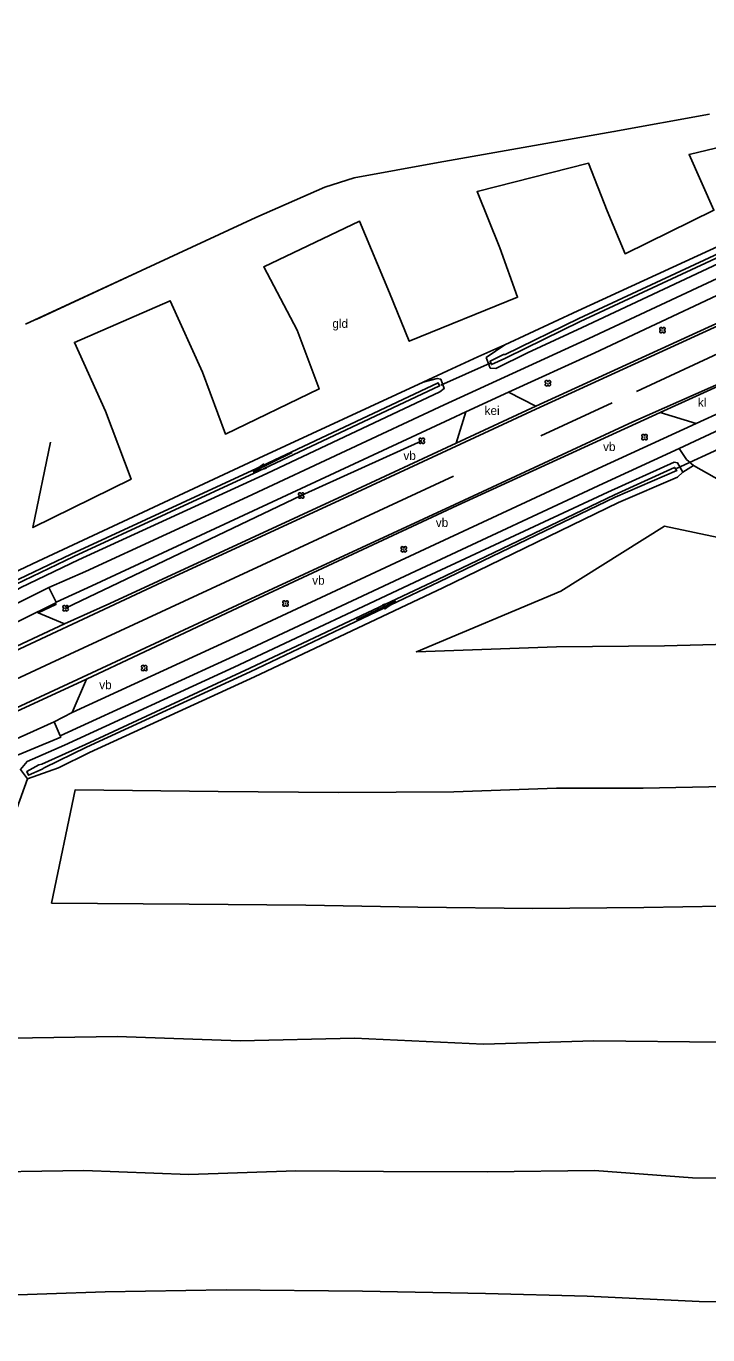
# Model space of a CAD drawing. Extents: x 154825 to 158680, y 370717 to 378075.
# Drawn here: x 157644.3 to 157722.1, y 372726.8 to 372876 of the extents above; entities that cross this region are included whole.
import ezdxf

# ---------------------------------------------------------------- set-up
doc = ezdxf.new("R2010")
doc.units = 0
for name, color, linetype in [('boom', 7, 'Continuous'), ('breuklijn', 7, 'Continuous'), ('cultuurscheiding', 7, 'Continuous'), ('deelstreep(3-9)', 7, 'Continuous'), ('duiker lijn', 7, 'Continuous'), ('grasland_productiegrasl(vs)', 7, 'Continuous'), ('hoogteverschillijn', 7, 'Continuous'), ('insteek sloot', 7, 'Continuous'), ('kantstreep', 7, 'Continuous'), ('keiverharding(vs)', 7, 'Continuous'), ('klinkerverharding(vs)', 7, 'Continuous'), ('maaiveldlijn algemeen - gesloten verharding', 7, 'Continuous'), ('maaiveldlijn algemeen - open verharding', 7, 'Continuous'), ('maaiveldlijn algemeen - tegelverharding', 7, 'Continuous'), ('raster - hek', 7, 'Continuous'), ('raster_hekw+inst', 7, 'Continuous'), ('Sloot bodem', 7, 'Continuous'), ('stroomrichting  watergangen', 7, 'Continuous'), ('verkeersb_z kabel', 7, 'Continuous'), ('vlak_akkerland', 7, 'Continuous'), ('vlak_Grasland', 7, 'Continuous'), ('vlak_Grazige_vegetatie', 7, 'Continuous')]:
    doc.layers.add(name, color=color, linetype=linetype)

msp = doc.modelspace()

# ---------------------------------------------------------------- linework, layer by layer
at = {"layer": 'boom'}
msp.add_lwpolyline([(157689.42, 372828.76), (157675.68, 372822.52), (157648.8, 372809.66)], dxfattribs=at)
for centre in [(157716.88, 372841.38), (157703.82, 372835.32), (157689.42, 372828.76), (157714.85, 372829.18), (157675.68, 372822.52), (157687.38, 372816.39), (157673.89, 372810.2), (157648.8, 372809.66), (157657.78, 372802.84)]:
    msp.add_circle(centre, 0.006, dxfattribs=at)
for centre, start, end in [((157716.72, 372841.54), 357.075, 272.925), ((157717.04, 372841.54), 267.075, 182.925), ((157716.72, 372841.22), 87.075, 2.925), ((157717.04, 372841.22), 177.075, 92.925), ((157703.66, 372835.48), 357.075, 272.925), ((157703.98, 372835.48), 267.075, 182.925), ((157703.66, 372835.16), 87.075, 2.925), ((157703.98, 372835.16), 177.075, 92.925), ((157689.27, 372828.92), 357.075, 272.925), ((157689.27, 372828.6), 87.075, 2.925), ((157689.58, 372828.92), 267.075, 182.925), ((157689.58, 372828.6), 177.075, 92.925), ((157714.69, 372829.34), 357.075, 272.925), ((157714.69, 372829.02), 87.075, 2.925), ((157715, 372829.34), 267.075, 182.925), ((157715, 372829.02), 177.075, 92.925), ((157675.52, 372822.68), 357.075, 272.925), ((157675.52, 372822.36), 87.075, 2.925), ((157675.83, 372822.68), 267.075, 182.925), ((157675.83, 372822.36), 177.075, 92.925), ((157687.22, 372816.54), 357.075, 272.925), ((157687.22, 372816.23), 87.075, 2.925), ((157687.54, 372816.54), 267.075, 182.925), ((157687.54, 372816.23), 177.075, 92.925), ((157673.73, 372810.36), 357.075, 272.925), ((157673.73, 372810.05), 87.075, 2.925), ((157674.05, 372810.36), 267.075, 182.925), ((157674.05, 372810.05), 177.075, 92.925), ((157648.65, 372809.82), 357.075, 272.925), ((157648.65, 372809.5), 87.075, 2.925), ((157648.96, 372809.82), 267.075, 182.925), ((157648.96, 372809.5), 177.075, 92.925), ((157657.62, 372803), 357.075, 272.925), ((157657.62, 372802.69), 87.075, 2.925), ((157657.93, 372803), 267.075, 182.925), ((157657.93, 372802.69), 177.075, 92.925)]:
    msp.add_arc(centre, 0.158, start, end, dxfattribs=at)
at = {"layer": 'breuklijn'}
msp.add_lwpolyline([(157587.11, 372729.57), (157594.94, 372731.25), (157612.07, 372732.63), (157623.63, 372737.63), (157631.2, 372747.28), (157634.47, 372759.97), (157641.12, 372779.89), (157643.22, 372786.82), (157644.44, 372790.21)], dxfattribs=at)
at = {"layer": 'cultuurscheiding'}
msp.add_lwpolyline([(157719.21, 372825.17), (157720.42, 372825.93)], dxfattribs=at)
at = {"layer": 'deelstreep(3-9)'}
msp.add_lwpolyline([(157693.04, 372824.71), (157671.19, 372814.57), (157649.3, 372804.41), (157627.44, 372794.27), (157604.56, 372783.62), (157594.54, 372778.92), (157572.69, 372768.8), (157551.11, 372758.81), (157529.26, 372748.71), (157507.38, 372738.56), (157474.53, 372723.31), (157452.88, 372713.29), (157431.04, 372703.17), (157418.74, 372697.46), (157398.09, 372687.91), (157373.81, 372676.65), (157351.94, 372666.54), (157329.99, 372656.33)], dxfattribs=at)
at = {"layer": 'duiker lijn'}
for points in [[(157691.59, 372835.12), (157697.22, 372837.6)], [(157718.5, 372825.61), (157729.04, 372830.46)]]:
    msp.add_lwpolyline(points, dxfattribs=at)
at = {"layer": 'hoogteverschillijn'}
for points in [[(157645.43, 372842.58), (157657.45, 372848.19), (157670.51, 372854.24), (157678.38, 372857.67), (157681.73, 372858.74), (157691.3, 372860.49), (157711.35, 372864.02), (157722.23, 372866.02)], [(157729.57, 372863.72), (157719.92, 372861.42), (157722.75, 372855.05), (157712.62, 372850.1), (157710.59, 372854.99), (157708.45, 372860.41), (157695.74, 372857.19), (157698.33, 372850.77), (157700.36, 372845.14), (157688, 372840.12), (157685.75, 372845.64), (157682.33, 372853.8), (157671.41, 372848.6), (157675.23, 372841.37), (157677.73, 372834.67), (157667.03, 372829.53), (157664.4, 372836.59), (157660.74, 372844.74), (157649.8, 372839.98), (157653.36, 372832.14), (157656.26, 372824.37), (157645.08, 372818.87), (157647.07, 372828.61)], [(157734.61, 372805.82), (157717.11, 372805.36), (157704.8, 372805.27), (157688.82, 372804.71), (157705.28, 372811.63), (157717.1, 372819.03), (157732.77, 372815.73)], [(157728.1, 372775.77), (157714.76, 372775.52), (157702.1, 372775.42), (157688.99, 372775.56), (157676.22, 372775.79), (157662.89, 372775.92), (157647.21, 372776.04), (157649.89, 372788.94), (157666.22, 372788.75), (157679.92, 372788.64), (157693.08, 372788.73), (157704.81, 372789.14), (157714.7, 372789.16), (157724.02, 372789.35)], [(157642.64, 372760.62), (157654.69, 372760.81), (157668.71, 372760.32), (157681.74, 372760.64), (157696.46, 372759.93), (157709.07, 372760.34), (157723.63, 372760.19)], [(157639.97, 372731.24), (157653.31, 372731.72), (157667.11, 372731.93), (157682.68, 372731.78), (157696.7, 372731.51), (157708.31, 372731.21), (157721.08, 372730.61), (157731.24, 372730.43), (157736.41, 372730.09), (157741.03, 372744.34), (157731.27, 372744.59), (157720.31, 372744.69), (157709.14, 372745.53), (157696.93, 372745.39), (157685.05, 372745.44), (157675.08, 372745.51), (157662.84, 372745.08), (157650.89, 372745.54), (157636.49, 372745.31)]]:
    msp.add_lwpolyline(points, dxfattribs=at)
at = {"layer": 'insteek sloot'}
for points in [[(157751.9, 372864.24), (157752.78, 372863.92), (157752.1, 372862.41), (157743.23, 372858.24), (157732.59, 372853.35), (157707.71, 372841.7), (157701.49, 372838.79), (157697.86, 372837.02), (157697.23, 372837.05), (157696.78, 372838.25), (157698.92, 372839.7)], [(157689.59, 372835.43), (157691.19, 372835.87), (157691.59, 372835.78), (157692, 372834.72), (157691.48, 372834.35), (157671.74, 372825.02), (157650.28, 372815.17), (157643.7, 372812.04), (157640.77, 372810.28), (157639.96, 372810.48), (157639.54, 372811.41), (157639.75, 372811.99), (157641.4, 372813.01)], [(157644.44, 372790.21), (157643.64, 372791.27), (157644.41, 372792.19), (157648.67, 372794.06), (157668.04, 372802.96), (157690.49, 372813.51), (157710.64, 372822.89), (157718.2, 372826.32), (157718.6, 372826.23), (157719.21, 372825.17)], [(157719.21, 372825.17), (157718.61, 372824.62), (157711.88, 372821.74), (157691.83, 372811.98), (157670.33, 372801.83), (157651.54, 372793.2), (157647.98, 372791.46), (157644.44, 372790.21)]]:
    msp.add_lwpolyline(points, dxfattribs=at)
at = {"layer": 'kantstreep'}
for points in [[(157810.64, 372876.05), (157801.79, 372871.94), (157775.86, 372859.77), (157754.32, 372849.16), (157753.47, 372848.81), (157743.28, 372844.03), (157725.96, 372836.42), (157713.52, 372830.91), (157693.18, 372821.51), (157668.95, 372810.3), (157650.14, 372801.55), (157633.01, 372793.59), (157612.56, 372784.08), (157591.65, 372774.31), (157568.57, 372763.65), (157543.05, 372751.84), (157518.22, 372740.35), (157495.3, 372729.73), (157482.15, 372723.63), (157473.39, 372719.56)], [(157758.12, 372858.41), (157746.58, 372853.32), (157739.86, 372850.21), (157734.79, 372847.6), (157723.69, 372842.09), (157702.45, 372832.35), (157680.99, 372822.41), (157659.83, 372812.62), (157637.52, 372802.23), (157632.78, 372800), (157617.21, 372792.78), (157595.92, 372782.87), (157569.75, 372770.75), (157543.55, 372758.61), (157517.06, 372746.36), (157486.41, 372732.15), (157469.86, 372724.47), (157454.4, 372717.29), (157430.13, 372706.05), (157404.83, 372694.32), (157376.21, 372681.02), (157354.77, 372671.07), (157328.63, 372658.97)], [(157729.2, 372841.48), (157735.46, 372844.21), (157736.24, 372844.56), (157738.92, 372845.67), (157741.38, 372846.55), (157741.3, 372847.47), (157738.07, 372845.78), (157733.78, 372843.67), (157729.2, 372841.48), (157713.91, 372834.37)], [(157711.16, 372833.08), (157703, 372829.32)]]:
    msp.add_lwpolyline(points, dxfattribs=at)
at = {"layer": 'maaiveldlijn algemeen - gesloten verharding'}
for points in [[(157759.78, 372864.31), (157751.08, 372860.26), (157729.63, 372850.3), (157708.49, 372840.44), (157691.99, 372832.86), (157669.54, 372822.37), (157651.06, 372813.84), (157646.9, 372812.04)], [(157749.86, 372857.68), (157730.06, 372848.6), (157709.18, 372838.81), (157699.32, 372834.29)], [(157702.42, 372832.7), (157723.46, 372842.31), (157734.66, 372847.86), (157739.16, 372850.13), (157750.38, 372855.42), (157750.78, 372855.74)], [(157651.19, 372801.57), (157669.09, 372810.02), (157693.47, 372821.4), (157716.63, 372831.97), (157725.24, 372835.89)], [(157699.32, 372834.29), (157694.46, 372832.05), (157692.66, 372831.22), (157670.19, 372820.79), (157651.81, 372812.21), (157647.72, 372810.35)], [(157702.42, 372832.7), (157693.36, 372828.49), (157680.9, 372822.7), (157653.85, 372810.19), (157648.67, 372807.88)], [(157649.56, 372797.76), (157668.96, 372806.7), (157690.35, 372816.68), (157709.54, 372825.6), (157720.72, 372830.73), (157723.89, 372832.18)], [(157648.18, 372795.13), (157669.41, 372804.86), (157689.93, 372814.47), (157710.11, 372823.89), (157718.79, 372827.89), (157724.08, 372830.34)], [(157646.9, 372812.04), (157647.72, 372810.35)], [(157485.69, 372732.18), (157486.38, 372732.42), (157516.97, 372746.59), (157543.47, 372758.88), (157569.58, 372771.01), (157595.75, 372783.12), (157617.89, 372793.48), (157648.67, 372807.88)], [(157597.92, 372776.72), (157614.42, 372784.61), (157651.19, 372801.57)], [(157619.82, 372784.24), (157647.5, 372796.7), (157649.56, 372797.76)], [(157648.18, 372795.13), (157647.5, 372796.7)]]:
    msp.add_lwpolyline(points, dxfattribs=at)
at = {"layer": 'maaiveldlijn algemeen - open verharding'}
for points in [[(157699.32, 372834.29), (157702.42, 372832.7)], [(157694.46, 372832.05), (157693.36, 372828.49)], [(157716.63, 372831.97), (157720.72, 372830.73)], [(157720.42, 372825.93), (157719.64, 372826.62), (157718.79, 372827.89)], [(157749.43, 372809.84), (157730.72, 372820.14), (157720.42, 372825.93)], [(157647.76, 372810.32), (157647.62, 372810.25), (157647.7, 372810.09)], [(157647.62, 372810.25), (157647.7, 372810.09)], [(157647.7, 372810.09), (157645.67, 372809.13), (157648.67, 372807.88)], [(157649.56, 372797.76), (157651.19, 372801.57)]]:
    msp.add_lwpolyline(points, dxfattribs=at)
at = {"layer": 'maaiveldlijn algemeen - tegelverharding'}
for points in [[(157641.42, 372809.29), (157646.9, 372812.04)], [(157647.62, 372810.25), (157640.21, 372806.58), (157632.57, 372802.8), (157627.94, 372800.65), (157620.39, 372797.49), (157616.62, 372795.93)], [(157647.72, 372810.35), (157647.76, 372810.32)], [(157641.94, 372792.32), (157648.24, 372794.96), (157648.18, 372795.13)]]:
    msp.add_lwpolyline(points, dxfattribs=at)
at = {"layer": 'raster - hek'}
msp.add_lwpolyline([(157698.92, 372839.7), (157695.82, 372838.32), (157692.35, 372836.73), (157689.59, 372835.43)], dxfattribs=at)
at = {"layer": 'raster_hekw+inst'}
for points in [[(157698.92, 372839.7), (157707.21, 372843.57), (157733.11, 372855.48), (157742.64, 372860), (157751.9, 372864.24)], [(157689.59, 372835.43), (157670.86, 372826.77), (157645.67, 372815.05), (157641.4, 372813.01)]]:
    msp.add_lwpolyline(points, dxfattribs=at)
at = {"layer": 'Sloot bodem'}
for points in [[(157751.74, 372863.24), (157747.36, 372861), (157733.4, 372854.4), (157707.5, 372842.35), (157699.12, 372838.25), (157698.92, 372838.15), (157697.38, 372837.46), (157697.22, 372837.84), (157698.76, 372838.59), (157698.94, 372838.59), (157707.36, 372842.7), (157733.25, 372854.75), (157747.12, 372861.36), (157751.74, 372863.24)], [(157691.3, 372835.37), (157691.46, 372835.02), (157670.79, 372825.29), (157649.73, 372815.58), (157642.14, 372811.91), (157641.73, 372811.7), (157640.24, 372811.06), (157640.07, 372811.48), (157641.54, 372812.14), (157641.78, 372812.19), (157649.43, 372815.83), (157670.59, 372825.61), (157691.3, 372835.37)], [(157718.52, 372825.36), (157718.27, 372825.73), (157711.42, 372822.58), (157691.26, 372812.95), (157669.82, 372802.83), (157651.06, 372794.12), (157646.07, 372791.87), (157645.74, 372791.79), (157644.37, 372791.04), (157644.58, 372790.62), (157646.11, 372791.31), (157646.34, 372791.45), (157651.17, 372793.81), (157669.84, 372802.43), (157691.42, 372812.66), (157711.48, 372822.32), (157718.52, 372825.36)]]:
    msp.add_lwpolyline(points, dxfattribs=at)
at = {"layer": 'stroomrichting  watergangen'}
for p, q in [((157674.64, 372827.42), (157670.16, 372825.21)), ((157670.16, 372825.21), (157671.43, 372826.15)), ((157670.18, 372825.21), (157671.7, 372825.65)), ((157681.97, 372808.33), (157686.48, 372810.46)), ((157686.46, 372810.47), (157684.94, 372810.05)), ((157686.48, 372810.46), (157685.19, 372809.55))]:
    msp.add_line(p, q, dxfattribs=at)
at = {"layer": 'vlak_akkerland'}
msp.add_lwpolyline([(157643.22, 372786.82), (157644.44, 372790.21), (157647.98, 372791.46), (157651.54, 372793.2), (157670.33, 372801.83), (157691.83, 372811.98), (157711.88, 372821.74), (157718.61, 372824.62), (157719.21, 372825.17), (157720.42, 372825.93), (157730.72, 372820.14)], dxfattribs=at)
at = {"layer": 'vlak_Grasland'}
for points in [[(157644.23, 372842.08), (157657.45, 372848.19), (157670.51, 372854.24), (157678.38, 372857.67), (157681.73, 372858.74), (157691.3, 372860.49), (157711.35, 372864.02), (157722.23, 372866.02)], [(157733.11, 372855.48), (157707.21, 372843.57), (157698.92, 372839.7), (157695.82, 372838.32), (157692.35, 372836.73), (157689.59, 372835.43), (157670.86, 372826.77), (157645.67, 372815.05), (157641.4, 372813.01)]]:
    msp.add_lwpolyline(points, dxfattribs=at)
at = {"layer": 'vlak_Grazige_vegetatie'}
for points in [[(157752.78, 372863.92), (157752.1, 372862.41), (157743.23, 372858.24), (157732.59, 372853.35), (157707.71, 372841.7), (157701.49, 372838.79), (157697.86, 372837.02), (157697.23, 372837.05), (157696.78, 372838.25), (157698.92, 372839.7), (157707.21, 372843.57), (157733.11, 372855.48), (157742.64, 372860), (157751.9, 372864.24)], [(157707.36, 372842.7), (157698.94, 372838.59), (157698.76, 372838.59), (157697.22, 372837.84), (157697.38, 372837.46), (157698.92, 372838.15), (157699.12, 372838.25), (157707.5, 372842.35), (157733.4, 372854.4), (157747.36, 372861), (157751.74, 372863.24), (157747.12, 372861.36), (157733.25, 372854.75)], [(157750.37, 372856.73), (157750.78, 372855.74), (157750.38, 372855.42), (157739.16, 372850.13), (157734.66, 372847.86), (157723.46, 372842.31), (157702.42, 372832.7), (157699.32, 372834.29), (157709.18, 372838.81), (157730.06, 372848.6), (157749.86, 372857.68)], [(157691.59, 372835.78), (157692, 372834.72), (157691.48, 372834.35), (157671.74, 372825.02), (157650.28, 372815.17), (157643.7, 372812.04), (157640.77, 372810.28), (157639.96, 372810.48), (157639.54, 372811.41), (157639.75, 372811.99), (157641.4, 372813.01), (157645.67, 372815.05), (157670.86, 372826.77), (157689.59, 372835.43), (157691.19, 372835.87)], [(157640.07, 372811.48), (157640.24, 372811.06), (157641.73, 372811.7), (157642.14, 372811.91), (157649.73, 372815.58), (157670.79, 372825.29), (157691.46, 372835.02), (157691.3, 372835.37), (157670.59, 372825.61), (157649.43, 372815.83), (157641.78, 372812.19), (157641.54, 372812.14)], [(157653.85, 372810.19), (157648.67, 372807.88), (157645.67, 372809.13), (157647.7, 372810.09), (157647.62, 372810.25), (157647.76, 372810.32), (157647.72, 372810.35), (157651.81, 372812.21), (157670.19, 372820.79), (157692.66, 372831.22), (157694.46, 372832.05), (157693.36, 372828.49), (157680.9, 372822.7)], [(157668.96, 372806.7), (157649.56, 372797.76), (157651.19, 372801.57), (157669.09, 372810.02), (157693.47, 372821.4), (157716.63, 372831.97), (157720.72, 372830.73), (157709.54, 372825.6), (157690.35, 372816.68)], [(157718.6, 372826.23), (157719.21, 372825.17), (157718.61, 372824.62), (157711.88, 372821.74), (157691.83, 372811.98), (157670.33, 372801.83), (157651.54, 372793.2), (157647.98, 372791.46), (157644.44, 372790.21), (157643.64, 372791.27), (157644.41, 372792.19), (157648.67, 372794.06), (157668.04, 372802.96), (157690.49, 372813.51), (157710.64, 372822.89), (157718.2, 372826.32)], [(157644.37, 372791.04), (157644.58, 372790.62), (157646.11, 372791.31), (157646.34, 372791.45), (157651.17, 372793.81), (157669.84, 372802.43), (157691.42, 372812.66), (157711.48, 372822.32), (157718.52, 372825.36), (157718.27, 372825.73), (157711.42, 372822.58), (157691.26, 372812.95), (157669.82, 372802.83), (157651.06, 372794.12), (157646.07, 372791.87), (157645.74, 372791.79)]]:
    msp.add_lwpolyline(points, close=True, dxfattribs=at)
for points in [[(157643.7, 372812.04), (157650.28, 372815.17), (157671.74, 372825.02), (157691.48, 372834.35), (157692, 372834.72), (157691.59, 372835.78), (157691.19, 372835.87), (157689.59, 372835.43), (157692.35, 372836.73), (157695.82, 372838.32), (157698.92, 372839.7), (157696.78, 372838.25), (157697.23, 372837.05), (157697.86, 372837.02), (157701.49, 372838.79), (157707.71, 372841.7), (157732.59, 372853.35)], [(157729.63, 372850.3), (157708.49, 372840.44), (157691.99, 372832.86), (157669.54, 372822.37), (157651.06, 372813.84), (157646.9, 372812.04), (157641.42, 372809.29)], [(157641.94, 372792.32), (157648.24, 372794.96), (157648.18, 372795.13), (157669.41, 372804.86), (157689.93, 372814.47), (157710.11, 372823.89), (157718.79, 372827.89), (157719.64, 372826.62), (157720.42, 372825.93), (157719.21, 372825.17), (157718.6, 372826.23), (157718.2, 372826.32), (157710.64, 372822.89), (157690.49, 372813.51), (157668.04, 372802.96), (157648.67, 372794.06), (157644.41, 372792.19), (157643.64, 372791.27), (157644.44, 372790.21), (157643.22, 372786.82)]]:
    msp.add_lwpolyline(points, dxfattribs=at)

# ---------------------------------------------------------------- texts
at = {"layer": 'grasland_productiegrasl(vs)'}
msp.add_text('gld', height=1, dxfattribs=at).set_placement((157679.23, 372841.64))
at = {"layer": 'keiverharding(vs)'}
msp.add_text('kei', height=1, dxfattribs=at).set_placement((157696.6, 372831.71))
at = {"layer": 'klinkerverharding(vs)'}
msp.add_text('kl', height=1, dxfattribs=at).set_placement((157720.92, 372832.64))
at = {"layer": 'verkeersb_z kabel'}
for p in [(157710.11, 372827.59), (157687.34, 372826.57), (157691.03, 372818.93), (157676.93, 372812.35), (157652.64, 372800.43)]:
    msp.add_text('vb', height=1, dxfattribs=at).set_placement(p)

doc.saveas('drawing.dxf')
